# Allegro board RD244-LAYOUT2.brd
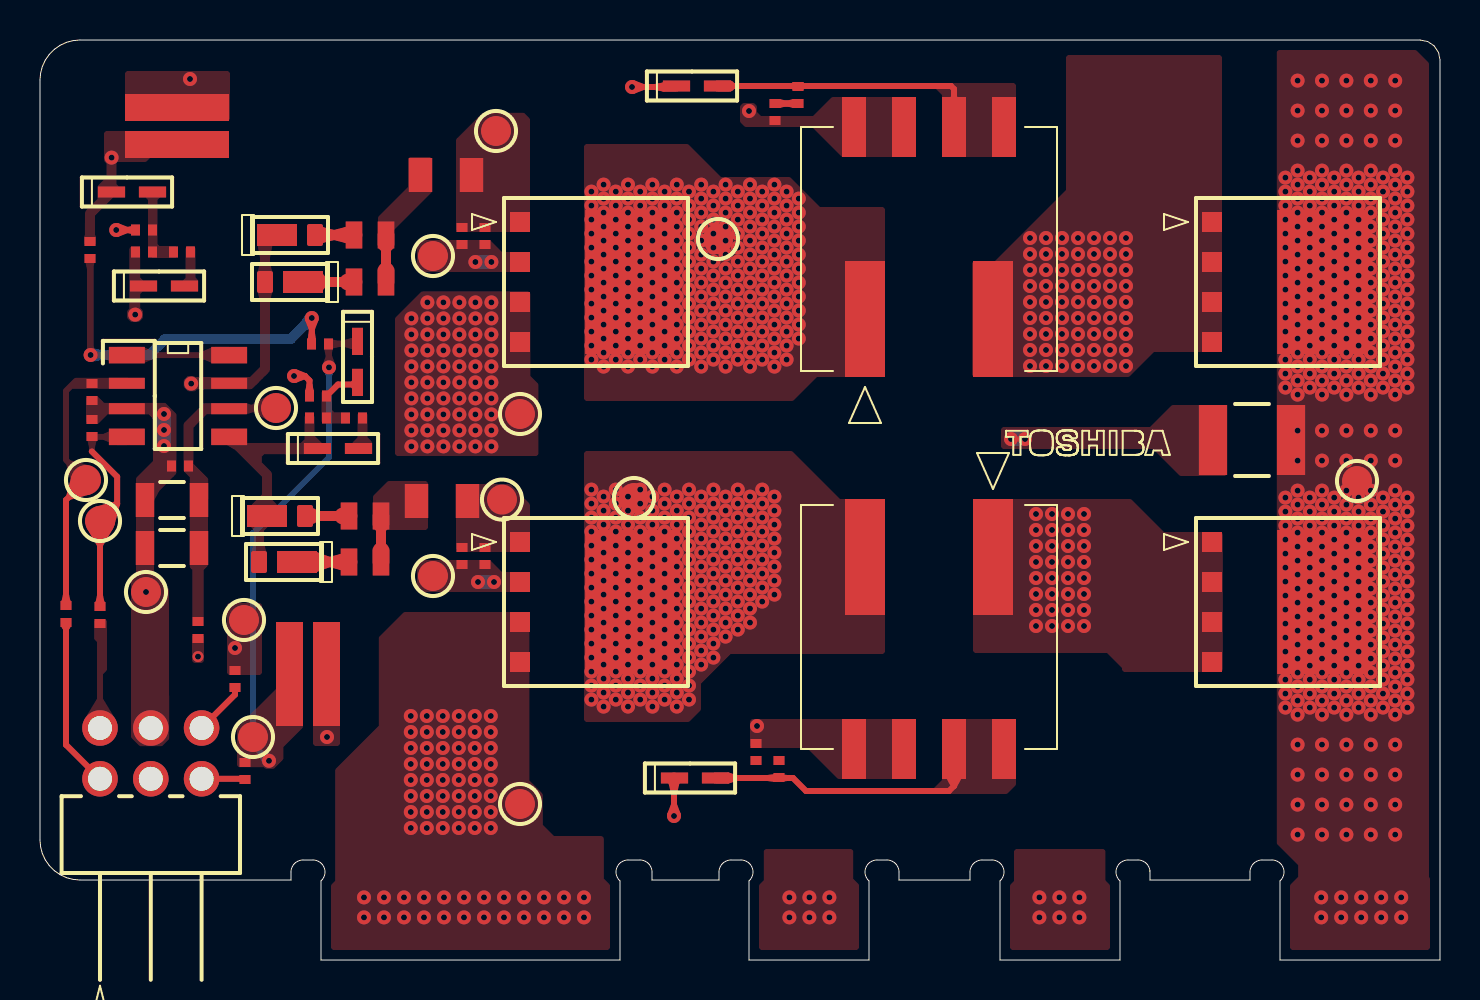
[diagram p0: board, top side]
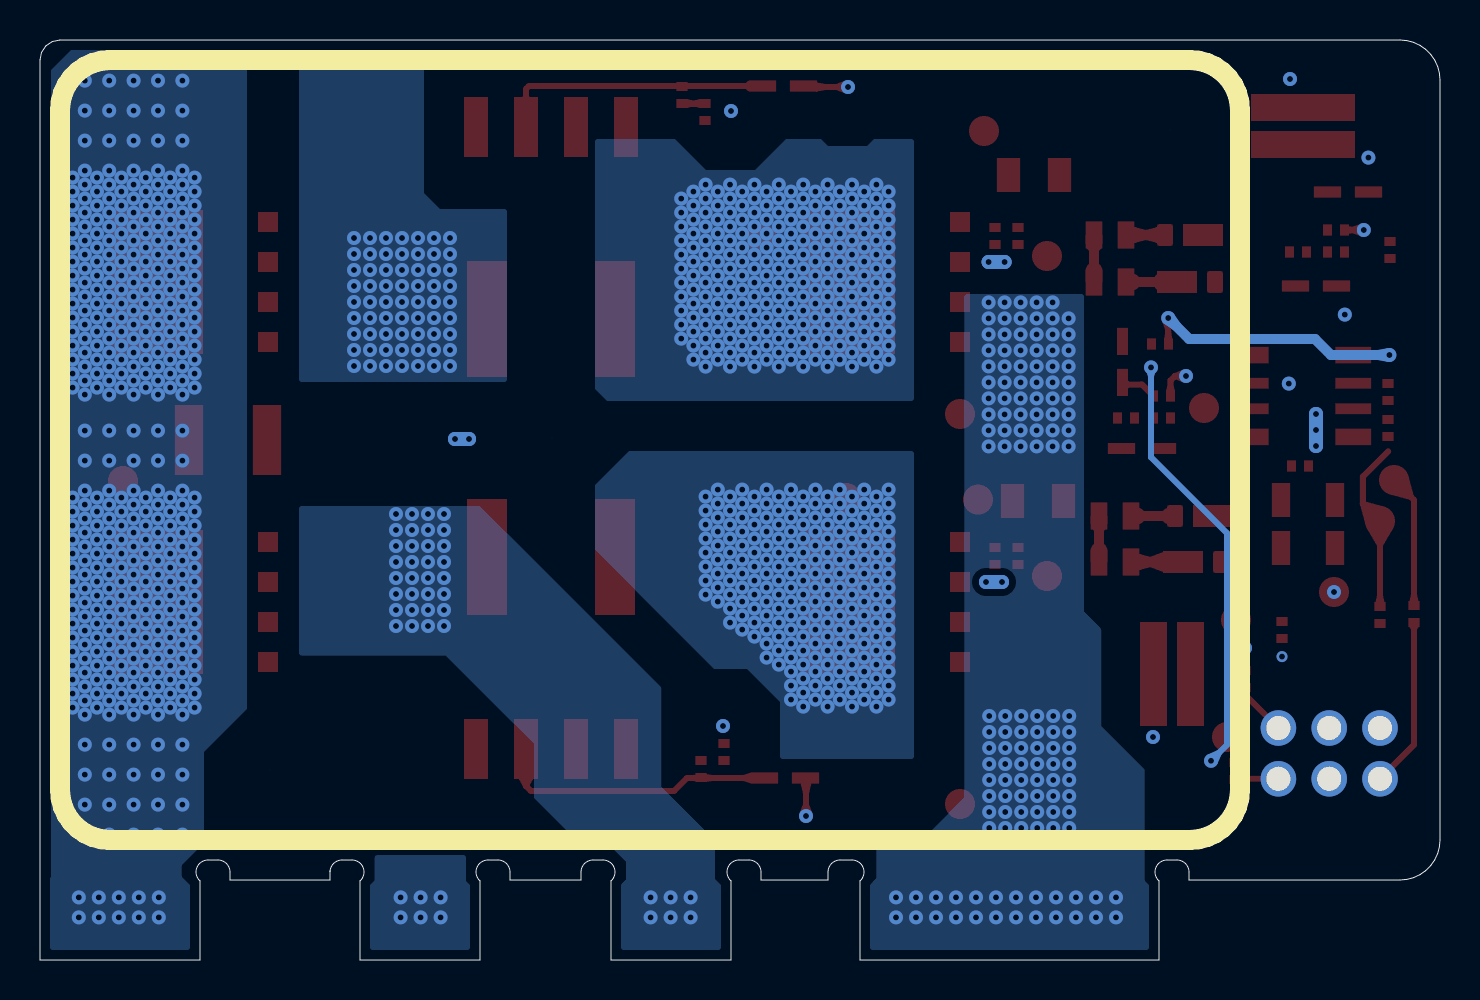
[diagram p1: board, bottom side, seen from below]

Outline 70 x 46 mm; copper layers: TOP, CONDUCTIVE2, CONDUCTIVE3, CONDUCTIVE4, CONDUCTIVE5, BOTTOM. Coordinates in mm from the lower left corner of the outline.
Outline path: 0,44 0.03,44.35 0.12,44.68 0.27,45 0.47,45.29 0.71,45.53 1,45.73 1.32,45.88 1.65,45.97 2,46 69,46 69.39,45.92 69.71,45.71 69.93,45.37 70,45 70,0 62,0 62,3.95 arc(62.16,4.61) 61.6,5 61.1,5 arc(60.68,4.82) 60.5,4.4 60.5,4 55.5,4 55.5,4.45 55.5,4.45 arc(55.31,4.84) 54.9,5 54.4,5 arc(53.84,4.61) 54,3.95 54,0 48,0 48,3.95 arc(48.16,4.61) 47.6,5 47.1,5 arc(46.68,4.82) 46.5,4.4 46.5,4 42.95,4 42.95,4.4 arc(42.77,4.82) 42.35,5 41.85,5 arc(41.29,4.61) 41.45,3.95 41.45,0 35.45,0 35.45,3.95 arc(35.61,4.61) 35.05,5 34.55,5 arc(34.13,4.82) 33.95,4.4 33.95,4 30.6,4 30.6,4.4 arc(30.42,4.82) 30,5 29.4,5 arc(28.84,4.61) 29,3.95 29,0 14.05,0 14.05,3.95 arc(14.21,4.61) 13.65,5 13.15,5 arc(12.73,4.82) 12.55,4.4 12.55,4 2,4 1.65,4.03 1.32,4.12 1,4.27 0.71,4.47 0.47,4.71 0.27,5 0.12,5.32 0.03,5.65 0,6 0,44

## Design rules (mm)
constraint set DEFAULT: 

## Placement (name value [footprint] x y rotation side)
C601  -  [FTP_65]  2.6 28.4 90 top
C602  -  [FTP_65]  2.6 26.6 270 top
C603  -  [FTP_15]  6.6 20.6 0 top
C604  -  [FTP_15]  6.6 23 0 top
C605  -  [FTP_65]  7 24.7 0 top
C606  -  [FTP_65]  36.75 42.4 90 top
C607  -  [FTP_65]  5.2 36.5 0 top
C608  -  [FTP_65]  35.8 10.4 270 top
C609  -  [FTP_65]  13.9 28.2 0 top
C610  -  [DC835R1AKP]  60.6 26 0 top
C611  -  [FTP_65]  22.25 36.2 90 top
C612  -  [FTP_65]  22.25 20.2 90 top
CN602  -  [CTP100H0ATP]  3 9.06 0 top
D601  -  [LOCAL_IDL02G65C5_A]  62.8 33.9 270 top
D602  -  [FTP_20]  32.85 43.7 180 top
D603  -  [US2H_A]  12.5 33.9 180 top
D604  -  [US2H_A]  12.5 36.25 0 top
D605  -  [FTP_20]  6.2 33.7 180 top
D606  -  [FTP_20]  4.6 38.4 180 top
D607  -  [LOCAL_IDL02G65C5_A]  62.8 17.9 270 top
D608  -  [FTP_20]  32.75 9.1 180 top
D609  -  [US2H_A]  12.2 19.9 180 top
D610  -  [US2H_A]  12 22.2 0 top
D611  -  [FTP_20]  14.9 25.57 180 top
D612  -  [FTP_20]  15.88 29.91 90 top
DP601  -  [DTP815]  2.3 24 0 top
DP602  -  [DTP815]  3 21.95 0 top
DP603  -  [DTP815]  11.8 27.6 0 top
DP604  -  [DTP815]  5.3 18.4 0 top
DP605  -  [DTP815]  10.2 17 0 top
DP606  -  [DTP815]  22.8 41.45 0 top
DP607  -  [DTP815]  33.9 36.05 0 top
DP608  -  [DTP815]  24 27.3 0 top
DP609  -  [DTP815]  10.65 11.15 0 top
DP610  -  [DTP815]  23.1 23.02 0 top
DP611  -  [DTP815]  29.7 23.1 0 top
DP612  -  [DTP815]  24 7.8 0 top
DP613  -  [DTP815]  65.85 23.95 0 top
DP614  -  [DTP815]  19.65 35.2 0 top
DP615  -  [DTP815]  19.65 19.2 0 top
IC601  -  [FTP_112]  6.9 28.2 270 top
L601  -  [FTP_55]  20.3 39.25 0 top
L602  -  [FTP_55]  20.1 22.95 0 top
NOREF  -  []  47.1 24.05 0 top
NOREF#2  -  [unnamed#2]  39.5 25.5 180 bottom
Q601  -  [LOCAL_DFN8X8_A]  28.2 33.9 270 top
Q602  -  [LOCAL_DFN8X8_A]  28.2 17.9 270 top
R601  -  [KC00050AKP]  7.9 16.5 90 top
R602  -  [KCK02780AKP]  6.85 41.7 270 top
R603  -  [KC00050AKP]  37.9 43.25 90 top
R604  -  [DR810K]  16.5 36.25 0 top
R605  -  [DR810K]  16.5 33.9 0 top
R606  -  [KC00050AKP]  21.1 36.2 90 top
R607  -  [KC00050AKP]  5.2 35.4 0 top
R608  -  [KC00050AKP]  7.1 35.4 180 top
R609  -  [KC00050AKP]  2.5 35.5 270 top
R610  -  [KCK02780AKP]  13.4 14.3 180 top
R611  -  [KC00050AKP]  36.95 9.55 270 top
R612  -  [DR810K]  16.25 22.2 0 top
R613  -  [DR810K]  16.25 19.9 0 top
R614  -  [KC00050AKP]  21.1 20.2 90 top
R615  -  [KC00050AKP]  13.9 27.1 0 top
R616  -  [KC00050AKP]  15.7 27.1 180 top
R617  -  [KC00050AKP]  14 30.8 180 top
R618  -  [KC00050AKP]  1.3 17.3 270 top
R619  -  [KC00050AKP]  3 17.25 270 top
R622  -  [KC00050AKP]  10.25 9.45 270 top
R623  -  [KC00050AKP]  9.75 14.05 270 top
T601  -  [LOCAL_PH9505_100NLT_A]  44.45 32.05 270 top
T602  -  [LOCAL_PH9505_100NLT_A]  44.45 20.15 90 top

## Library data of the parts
C601 C602 C605-C609 C611 C612 = PRT_52: alternate symbols: (T:FTP_65;B:FTP_66)
C603 C604 = PRT_46: alternate symbols: (T:FTP_15;B:FTP_16)
C610 = K03S007Y: alternate symbols: (T:DC835R1AKP;B:DC835R1BKP)
CN602 = K22S0030: alternate symbols: (T:CTP100H0ATP;B:CTP100H0BTP)
D601 D607 = TRS12V65H: alternate symbols: (T:Local_IDL02G65C5_A;B:Local_IDL02G65C5_B)
D602 D605 D606 D608 D611 D612 = PRT_27: alternate symbols: (T:FTP_20;B:FTP_22)
D603 D604 D609 D610 = CUHS15S30: alternate symbols: (T:US2H_A;B:US2H_B)
DP601-DP615 = DTP815: alternate symbols: (T:DTP815;B:DTP915)
IC601 = PRT_63: alternate symbols: (T:FTP_112;B:FTP_113)
L601 L602 = PRT_30: alternate symbols: (T:FTP_55;B:FTP_56)
Q601 Q602 = NchMOSFET_DFN8x8-01: alternate symbols: (T:Local_DFN8x8_A;B:Local_DFN8x8_B)
R601 R603 R606-R609 R611 R614-R619 R622 R623 = GDM010004481: alternate symbols: (T:KC00050AKP;B:KC00050BKP)
R602 R610 = K01S003U: alternate symbols: (T:KCK02780AKP;B:KCK02780BKP)
R604 R605 R612 R613 = R2012: alternate symbols: (T:DR810K;B:DR910K)
T601 T602 = PH9505_100NLT: alternate symbols: (T:Local_PH9505_100NLT_A;B:Local_PH9505_100NLT_B)

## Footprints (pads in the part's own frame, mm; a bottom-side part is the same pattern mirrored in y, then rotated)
CTP100H0ATP
  round 1.778 hole 1.2: 1(0,0) 2(0,2.54) 3(2.54,0) 4(2.54,2.54) 5(5.08,0) 6(5.08,2.54)
DC835R1AKP
  rect 1.41x3.5 smd: 1(-1.95,0) 2(1.95,0)
DR810K
  rect 0.83x1.35 smd: 1(-0.8,0) 2(0.8,0)
DTP815
  round 1.5 smd: 1(0,0)
FTP_15
  rect 0.92x1.7 smd: 1(-1.35,0) 2(1.35,0)
FTP_20
  rect 1.36x0.55 smd: A(-1.025,0) C(1.025,0)
FTP_55
  rect 1.17x1.7 smd: 1(-1.275,0) 2(1.275,0)
FTP_65
  rect 0.45x0.55 smd: 1(-0.425,0) 2(0.425,0)
FTP_112
  rect 0.825x1.795 smd: 1(-2.042,-2.558) 4(2.042,-2.558) 5(2.042,2.558) 8(-2.042,2.558)
  rect 0.55x1.795 smd: 2(-0.635,-2.558) 3(0.635,-2.558) 6(0.635,2.558) 7(-0.635,2.558)
KC00050AKP
  rect 0.45x0.55 smd: 1(-0.425,0) 2(0.425,0)
KCK02780AKP
  rect 1.35x5.2 smd: 1(-0.925,0) 2(0.925,0)
LOCAL_DFN8X8_A
  rect 1x1 smd: 1(-3,-4.2) 2(-1,-4.2) 3(1,-4.2) 4(3,-4.2)
  rect 7.2x4.75 smd: 5(0,1.43)
LOCAL_IDL02G65C5_A
  rect 1x1 smd: 1(-3,-4.2) 2(-1,-4.2) 3(1,-4.2) 4(3,-4.2)
  rect 7.2x4.75 smd: 5(0,1.43)
LOCAL_PH9505_100NLT_A
  rect 5.8x2 smd: 1(0,-3.2) 2(0,3.2)
  rect 3x1.2 smd: 3(-9.6,3.75) 4(-9.6,1.25) 5(-9.6,-1.25) 6(-9.6,-3.75)
unnamed#2
  round 0.01 hole 3.2 unplated: (-19,-16) (-4.9,0.6) (26,16)
US2H_A
  custom 0.2x0.2 smd: A(1.25,0)
  rect 2x1.1 smd: C(-0.65,0)

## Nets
VCC18R0_1: CN602.3 IC601.1 IC601.8 R601.1 R609.2 R617.2
CSA: CN602.6 D602.C D606.C DP605.1 R602.2 R609.1 R623.1 R623.2
CSB: CN602.5 D608.C D612.C DP609.1 R610.2 R617.1 R622.1 R622.2
GDA: C601.2 CN602.1 DP601.1 IC601.2 R618.1 R618.2
GDB: C602.2 CN602.2 DP602.1 IC601.4 R619.1 R619.2
PN: C601.1 C602.1 C603.1 C604.1 C605.1 C606.1 C607.1 C608.1 C609.1 C611.1 C612.1 CN602.4 DP604.1 DP614.1 DP615.1 IC601.3 Q601.2 Q602.2 R602.1 R606.1 R610.1 R614.1 T601.5 T602.4
SIG0017: C612.2 D609.C D610.A DP610.1 L602.1 L602.2 Q602.1 R612.1 R612.2 R613.1 R613.2 R614.2
SIG0019: C609.2 D609.A D610.C D611.A D611.C D612.A IC601.5 R615.1 R615.2 R616.1 R616.2
SIG00110: C611.2 D603.C D604.A DP606.1 L601.1 L601.2 Q601.1 R604.1 R604.2 R605.1 R605.2 R606.2
SIG00112: C607.2 D603.A D604.C D605.A D605.C D606.A IC601.7 R607.1 R607.2 R608.1 R608.2
SIG00119: C603.2 C604.2 C605.2 DP603.1 IC601.6 R601.2
SIG00120: D607.3 D607.4 T602.1
SIG00125: DP607.1 Q601.5 T601.1
SIG00126: C608.2 D608.A R611.1 R611.2 T602.5
SIG00127: C606.2 D602.A R603.1 R603.2 T601.4
SIG00130: D601.3 D601.4 T601.2
SIG00131: DP611.1 Q602.5 T602.2
SIG00132: C610.1 C610.2 D601.5 D607.5 DP608.1 DP612.1 DP613.1 Q601.3 Q601.4 Q602.3 Q602.4

Pads without a net: D601 1 2; D607 1 2; T601 3 6; T602 3 6

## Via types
v1: diameter 0.7, hole 0.3, TOP to BOTTOM, 1140 vias
v2: diameter 0.55, hole 0.3, TOP to BOTTOM, 1 via

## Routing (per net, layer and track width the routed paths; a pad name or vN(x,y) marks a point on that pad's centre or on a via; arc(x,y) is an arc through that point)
VCC18R0_1: length 13.1
  TOP w0.3: v1(13.59,32.1) 13.59,30.98
  TOP w0.42: 13.59,30.98 13.59,30.8
  BOTTOM w0.5: v1(13.59,32.1) 12.54,31.05 6.25,31.05 5.45,30.25 v1(2.53,30.25)
  vias: v2(7.9,15.17)
CSA: length 62.2
  TOP w0.3: v1(29.6,43.65) 31.18,43.65 ; R623.2 9.75,13.27 CN602.6
  TOP w0.45: 31.18,43.65 31.82,43.65
  CONDUCTIVE4 w0.3: v1(3.58,40.12) 5.63,40.12 8.65,37.1 ; 8.65,37.1 9.05,37.1 ; 8.65,37.1 9.05,36.7 ; 9.05,37.1 9.05,36.7 ; 9.05,37.1 9.05,43.3 10.9,45.15 20.5,45.15 21.35,44.3 28.95,44.3 v1(29.6,43.65) ; 9.05,36.7 9.05,16.3 v1(9.75,15.6)
CSB: length 48.5
  TOP w0.3: v1(31.7,7.2) 31.7,8.89 ; CN602.5 10.08,9.06
  TOP w0.38: 10.08,9.06 10.25,9.06
  TOP w0.55: 31.7,8.89 31.7,9.1
  CONDUCTIVE4 w0.3: v1(11.45,9.96) 16.01,5.4 26.9,5.4 28.7,7.2 v1(31.7,7.2)
  BOTTOM w0.3: v1(11.45,9.96) 10.65,10.76 10.65,21.34 14.45,25.14 v1(14.45,29.63)
GDA: length 15.2
  TOP w0.3: 1.3,17.9 1.3,23 DP601.1 ; 1.3,16.7 1.3,10.76 CN602.1
  TOP w0.45: R618.1 1.3,17.9 ; 1.3,16.7 R618.2
GDB: length 8.6
  TOP w0.3: 3,17.85 DP602.1 3.86,22.81 3.86,24.16 2.59,25.43
  TOP w0.45: R619.1 3,17.85
PN: length 104.3
  TOP w0.3: v1(12.7,29.2) 13.25,29.2 13.47,28.98 13.47,28.38 ; v1(3.81,36.5) 4.73,36.5
  TOP w0.45: 4.73,36.5 C607.1 ; 13.47,28.38 C609.1
  CONDUCTIVE3 w0.3: v1(35.45,42.45) 20.05,42.45 17.55,44.95 8.4,44.95 v1(7.5,44.05) 7.5,32.6 5.3,30.4 v1(5.3,18.4) 9.95,18.4 14.35,14 v1(14.35,11.15) 14.35,9 17.85,5.5 26,5.5 26.7,6.2 32.45,6.2 35.85,9.6 v1(35.85,11.7)
  BOTTOM w0.7: v1(21.77,34.9) v1(22.57,34.9) ; v1(6.2,25.7) v1(6.2,26.5) v1(6.2,27.3) ; v1(22.7,18.9) v1(21.9,18.9)
SIG0017: length 7.1
  TOP w0.5: 15.14,22.2 13.56,22.2 ; 17.05,21.8 17.05,20.47 ; 15.14,19.9 13.59,19.9
  TOP w0.8: 13.56,22.2 D610.A
  TOP w0.83: R612.1 15.14,22.2 ; R612.2 17.05,21.8 ; 17.05,20.47 R613.2 ; R613.1 15.14,19.9
  TOP w1.1: 13.59,19.9 D609.C
SIG0019: length 1.7
  TOP w0.3: 15.79,28.77 14.9,28.77 14.32,28.2
  TOP w0.55: 15.8,28.77 15.79,28.77
SIG00110: length 6.8
  TOP w0.5: 17.3,35.8 17.3,34.47 ; 13.77,33.9 15.39,33.9 ; 14.06,36.25 15.39,36.25
  TOP w0.8: D604.A 14.06,36.25
  TOP w0.83: 17.3,34.47 R605.2 ; 15.39,36.25 R604.1 ; 15.39,33.9 R605.1 ; R604.2 17.3,35.8
  TOP w1.1: D603.C 13.77,33.9
SIG00112: length 5.6
  CONDUCTIVE4 w0.5: v1(7.56,28.82) 7.56,31.14 6.43,32.27 v1(4.76,32.27)
SIG00120:
  vias: v1(37.47,3.13) v1(37.47,2.13) v1(38.47,3.13) v1(38.47,2.13) v1(39.47,3.13) v1(39.47,2.13) v1(49.8,22.3) v1(49.8,21.5) v1(49.8,20.7) v1(49.8,19.9) v1(49.8,19.1) v1(49.8,18.3) v1(49.8,17.5) v1(49.8,16.7) v1(50.6,22.3) v1(50.6,21.5) v1(50.6,20.7) v1(50.6,19.9) v1(50.6,19.1) v1(50.6,18.3) v1(50.6,17.5) v1(50.6,16.7) v1(51.4,22.3) v1(51.4,21.5) v1(51.4,20.7) v1(51.4,19.9) v1(51.4,19.1) v1(51.4,18.3) v1(51.4,17.5) v1(51.4,16.7) v1(52.2,22.3) v1(52.2,21.5) v1(52.2,20.7) v1(52.2,19.9) v1(52.2,19.1) v1(52.2,18.3) v1(52.2,17.5) v1(52.2,16.7)
SIG00125:
  vias: v1(27.57,38.42) v1(27.57,37.72) v1(27.57,37.02) v1(27.57,36.32) v1(27.57,35.62) v1(27.57,34.92) v1(27.57,34.22) v1(27.57,33.52) v1(27.57,32.82) v1(27.57,32.12) v1(27.57,31.42) v1(27.57,30.72) v1(27.57,30.02) v1(28.18,38.77) v1(28.18,38.07) v1(28.18,37.37) v1(28.18,36.67) v1(28.18,35.97) v1(28.18,35.27) v1(28.18,34.57) v1(28.18,33.87) v1(28.18,33.17) v1(28.18,32.47) v1(28.18,31.77) v1(28.18,31.07) v1(28.18,30.37) v1(28.18,29.67) v1(28.79,38.42) v1(28.79,37.72) v1(28.79,37.02) v1(28.79,36.32) v1(28.79,35.62) v1(28.79,34.92) v1(28.79,34.22) v1(28.79,33.52) v1(28.79,32.82) v1(28.79,32.12) v1(28.79,31.42) v1(28.79,30.72) v1(28.79,30.02) v1(29.4,38.77) v1(29.4,38.07) v1(29.4,37.37) v1(29.4,36.67) v1(29.4,35.97) v1(29.4,35.27) v1(29.4,34.57) v1(29.4,33.87) v1(29.4,33.17) v1(29.4,32.47) v1(29.4,31.77) v1(29.4,31.07) v1(29.4,30.37) v1(29.4,29.67) v1(30.01,38.42) v1(30.01,37.72) v1(30.01,37.02) v1(30.01,36.32) v1(30.01,35.62) v1(30.01,34.92) v1(30.01,34.22) v1(30.01,33.52) v1(30.01,32.82) v1(30.01,32.12) v1(30.01,31.42) v1(30.01,30.72) v1(30.01,30.02) v1(30.62,38.77) v1(30.62,38.07) v1(30.62,37.37) v1(30.62,36.67) v1(30.62,35.97) v1(30.62,35.27) v1(30.62,34.57) v1(30.62,33.87) v1(30.62,33.17) v1(30.62,32.47) v1(30.62,31.77) v1(30.62,31.07) v1(30.62,30.37) v1(30.62,29.67) v1(31.23,38.42) v1(31.23,37.72) v1(31.23,37.02) v1(31.23,36.32) v1(31.23,35.62) v1(31.23,34.92) v1(31.23,34.22) v1(31.23,33.52) v1(31.23,32.82) v1(31.23,32.12) v1(31.23,31.42) v1(31.23,30.72) v1(31.23,30.02) v1(31.84,38.77) v1(31.84,38.07) v1(31.84,37.37) v1(31.84,36.67) v1(31.84,35.97) v1(31.84,35.27) v1(31.84,34.57) v1(31.84,33.87) v1(31.84,33.17) v1(31.84,32.47) v1(31.84,31.77) v1(31.84,31.07) v1(31.84,30.37) v1(31.84,29.67) v1(32.45,38.42) v1(32.45,37.72) v1(32.45,37.02) v1(32.45,36.32) v1(32.45,35.62) v1(32.45,34.92) v1(32.45,34.22) v1(32.45,33.52) v1(32.45,32.82) v1(32.45,32.12) v1(32.45,31.42) v1(32.45,30.72) v1(32.45,30.02) v1(33.06,38.77) v1(33.06,38.07) v1(33.06,37.37) v1(33.06,36.67) v1(33.06,35.97) v1(33.06,35.27) v1(33.06,34.57) v1(33.06,33.87) v1(33.06,33.17) v1(33.06,32.47) v1(33.06,31.77) v1(33.06,31.07) v1(33.06,30.37) v1(33.06,29.67) v1(33.67,38.42) v1(33.67,37.72) v1(33.67,37.02) v1(33.67,36.32) v1(33.67,35.62) v1(33.67,34.92) v1(33.67,34.22) v1(33.67,33.52) v1(33.67,32.82) v1(33.67,32.12) v1(33.67,31.42) v1(33.67,30.72) v1(33.67,30.02) v1(34.28,38.77) v1(34.28,38.07) v1(34.28,37.37) v1(34.28,36.67) v1(34.28,35.97) v1(34.28,35.27) v1(34.28,34.57) v1(34.28,33.87) v1(34.28,33.17) v1(34.28,32.47) v1(34.28,31.77) v1(34.28,31.07) v1(34.28,30.37) v1(34.28,29.67) v1(34.89,38.42) v1(34.89,37.72) v1(34.89,37.02) v1(34.89,36.32) v1(34.89,35.62) v1(34.89,34.92) v1(34.89,34.22) v1(34.89,33.52) v1(34.89,32.82) v1(34.89,32.12) v1(34.89,31.42) v1(34.89,30.72) v1(34.89,30.02) v1(35.5,38.77) v1(35.5,38.07) v1(35.5,37.37) v1(35.5,36.67) v1(35.5,35.97) v1(35.5,35.27) v1(35.5,34.57) v1(35.5,33.87) v1(35.5,33.17) v1(35.5,32.47) v1(35.5,31.77) v1(35.5,31.07) v1(35.5,30.37) v1(35.5,29.67) v1(36.11,38.42) v1(36.11,37.72) v1(36.11,37.02) v1(36.11,36.32) v1(36.11,35.62) v1(36.11,34.92) v1(36.11,34.22) v1(36.11,33.52) v1(36.11,32.82) v1(36.11,32.12) v1(36.11,31.42) v1(36.11,30.72) v1(36.11,30.02) v1(36.72,38.77) v1(36.72,38.07) v1(36.72,37.37) v1(36.72,36.67) v1(36.72,35.97) v1(36.72,35.27) v1(36.72,34.57) v1(36.72,33.87) v1(36.72,33.17) v1(36.72,32.47) v1(36.72,31.77) v1(36.72,31.07) v1(36.72,30.37) v1(36.72,29.67) v1(37.33,38.42) v1(37.33,37.72) v1(37.33,37.02) v1(37.33,36.32) v1(37.33,35.62) v1(37.33,34.92) v1(37.33,34.22) v1(37.33,33.52) v1(37.33,32.82) v1(37.33,32.12) v1(37.33,31.42) v1(37.33,30.72) v1(37.33,30.02) v1(37.94,38.07) v1(37.94,37.37) v1(37.94,36.67) v1(37.94,35.97) v1(37.94,35.27) v1(37.94,34.57) v1(37.94,33.87) v1(37.94,33.17) v1(37.94,32.47) v1(37.94,31.77) v1(37.94,31.07)
SIG00126: length 14.1
  TOP w0.3: 36.95,9.1 37.65,9.1 38.3,8.45 45.45,8.45 45.7,8.7 45.7,9.65 ; 34.38,9.1 36.77,9.1
  TOP w0.4: 36.77,9.1 36.95,9.1
  TOP w0.55: D608.A 34.38,9.1
  TOP w1.2: 45.7,9.65 T602.5
SIG00127: length 14.9
  TOP w0.3: 37.73,43.7 34.48,43.7 ; 45.7,42.59 45.7,43.55 45.55,43.7 38.07,43.7 ; 36.93,42.83 37.72,42.83
  TOP w0.4: 38.07,43.7 37.73,43.7
  TOP w0.45: 37.72,42.83 R603.1 ; C606.2 36.93,42.83
  TOP w0.55: 34.48,43.7 D602.A
  TOP w1.2: T601.4 45.7,42.59
SIG00130:
  vias: v1(49.5,36.1) v1(49.5,35.3) v1(49.5,34.5) v1(49.5,33.7) v1(49.5,32.9) v1(49.5,32.1) v1(49.5,31.3) v1(49.5,30.5) v1(49.5,29.7) v1(49.97,3.13) v1(49.97,2.13) v1(50.3,36.1) v1(50.3,35.3) v1(50.3,34.5) v1(50.3,33.7) v1(50.3,32.9) v1(50.3,32.1) v1(50.3,31.3) v1(50.3,30.5) v1(50.3,29.7) v1(50.97,3.13) v1(50.97,2.13) v1(51.1,36.1) v1(51.1,35.3) v1(51.1,34.5) v1(51.1,33.7) v1(51.1,32.9) v1(51.1,32.1) v1(51.1,31.3) v1(51.1,30.5) v1(51.1,29.7) v1(51.9,36.1) v1(51.9,35.3) v1(51.9,34.5) v1(51.9,33.7) v1(51.9,32.9) v1(51.9,32.1) v1(51.9,31.3) v1(51.9,30.5) v1(51.9,29.7) v1(51.97,3.13) v1(51.97,2.13) v1(52.7,36.1) v1(52.7,35.3) v1(52.7,34.5) v1(52.7,33.7) v1(52.7,32.9) v1(52.7,32.1) v1(52.7,31.3) v1(52.7,30.5) v1(52.7,29.7) v1(53.5,36.1) v1(53.5,35.3) v1(53.5,34.5) v1(53.5,33.7) v1(53.5,32.9) v1(53.5,32.1) v1(53.5,31.3) v1(53.5,30.5) v1(53.5,29.7) v1(54.3,36.1) v1(54.3,35.3) v1(54.3,34.5) v1(54.3,33.7) v1(54.3,32.9) v1(54.3,32.1) v1(54.3,31.3) v1(54.3,30.5) v1(54.3,29.7)
SIG00131:
  vias: v1(27.57,23.52) v1(27.57,22.82) v1(27.57,22.12) v1(27.57,21.42) v1(27.57,20.72) v1(27.57,20.02) v1(27.57,19.32) v1(27.57,18.62) v1(27.57,17.92) v1(27.57,17.22) v1(27.57,16.52) v1(27.57,15.82) v1(27.57,15.12) v1(27.57,14.42) v1(27.57,13.72) v1(27.57,13.02) v1(28.18,23.17) v1(28.18,22.47) v1(28.18,21.77) v1(28.18,21.07) v1(28.18,20.37) v1(28.18,19.67) v1(28.18,18.97) v1(28.18,18.27) v1(28.18,17.57) v1(28.18,16.87) v1(28.18,16.17) v1(28.18,15.47) v1(28.18,14.77) v1(28.18,14.07) v1(28.18,13.37) v1(28.18,12.67) v1(28.79,23.52) v1(28.79,22.82) v1(28.79,22.12) v1(28.79,21.42) v1(28.79,20.72) v1(28.79,20.02) v1(28.79,19.32) v1(28.79,18.62) v1(28.79,17.92) v1(28.79,17.22) v1(28.79,16.52) v1(28.79,15.82) v1(28.79,15.12) v1(28.79,14.42) v1(28.79,13.72) v1(28.79,13.02) v1(29.4,23.17) v1(29.4,22.47) v1(29.4,21.77) v1(29.4,21.07) v1(29.4,20.37) v1(29.4,19.67) v1(29.4,18.97) v1(29.4,18.27) v1(29.4,17.57) v1(29.4,16.87) v1(29.4,16.17) v1(29.4,15.47) v1(29.4,14.77) v1(29.4,14.07) v1(29.4,13.37) v1(29.4,12.67) v1(30.01,23.52) v1(30.01,22.82) v1(30.01,22.12) v1(30.01,21.42) v1(30.01,20.72) v1(30.01,20.02) v1(30.01,19.32) v1(30.01,18.62) v1(30.01,17.92) v1(30.01,17.22) v1(30.01,16.52) v1(30.01,15.82) v1(30.01,15.12) v1(30.01,14.42) v1(30.01,13.72) v1(30.01,13.02) v1(30.62,23.17) v1(30.62,22.47) v1(30.62,21.77) v1(30.62,21.07) v1(30.62,20.37) v1(30.62,19.67) v1(30.62,18.97) v1(30.62,18.27) v1(30.62,17.57) v1(30.62,16.87) v1(30.62,16.17) v1(30.62,15.47) v1(30.62,14.77) v1(30.62,14.07) v1(30.62,13.37) v1(30.62,12.67) v1(31.23,23.52) v1(31.23,22.82) v1(31.23,22.12) v1(31.23,21.42) v1(31.23,20.72) v1(31.23,20.02) v1(31.23,19.32) v1(31.23,18.62) v1(31.23,17.92) v1(31.23,17.22) v1(31.23,16.52) v1(31.23,15.82) v1(31.23,15.12) v1(31.23,14.42) v1(31.23,13.72) v1(31.23,13.02) v1(31.84,23.17) v1(31.84,22.47) v1(31.84,21.77) v1(31.84,21.07) v1(31.84,20.37) v1(31.84,19.67) v1(31.84,18.97) v1(31.84,18.27) v1(31.84,17.57) v1(31.84,16.87) v1(31.84,16.17) v1(31.84,15.47) v1(31.84,14.77) v1(31.84,14.07) v1(31.84,13.37) v1(31.84,12.67) v1(32.45,23.52) v1(32.45,22.82) v1(32.45,22.12) v1(32.45,21.42) v1(32.45,20.72) v1(32.45,20.02) v1(32.45,19.32) v1(32.45,18.62) v1(32.45,17.92) v1(32.45,17.22) v1(32.45,16.52) v1(32.45,15.82) v1(32.45,15.12) v1(32.45,14.42) v1(32.45,13.72) v1(32.45,13.02) v1(33.06,23.17) v1(33.06,22.47) v1(33.06,21.77) v1(33.06,21.07) v1(33.06,20.37) v1(33.06,19.67) v1(33.06,18.97) v1(33.06,18.27) v1(33.06,17.57) v1(33.06,16.87) v1(33.06,16.17) v1(33.06,15.47) v1(33.06,14.77) v1(33.67,23.52) v1(33.67,22.82) v1(33.67,22.12) v1(33.67,21.42) v1(33.67,20.72) v1(33.67,20.02) v1(33.67,19.32) v1(33.67,18.62) v1(33.67,17.92) v1(33.67,17.22) v1(33.67,16.52) v1(33.67,15.82) v1(33.67,15.12) v1(34.28,23.17) v1(34.28,22.47) v1(34.28,21.77) v1(34.28,21.07) v1(34.28,20.37) v1(34.28,19.67) v1(34.28,18.97) v1(34.28,18.27) v1(34.28,17.57) v1(34.28,16.87) v1(34.28,16.17) v1(34.89,23.52) v1(34.89,22.82) v1(34.89,22.12) v1(34.89,21.42) v1(34.89,20.72) v1(34.89,20.02) v1(34.89,19.32) v1(34.89,18.62) v1(34.89,17.92) v1(34.89,17.22) v1(34.89,16.52) v1(35.5,23.17) v1(35.5,22.47) v1(35.5,21.77) v1(35.5,21.07) v1(35.5,20.37) v1(35.5,19.67) v1(35.5,18.97) v1(35.5,18.27) v1(35.5,17.57) v1(35.5,16.87) v1(36.11,23.52) v1(36.11,22.82) v1(36.11,22.12) v1(36.11,21.42) v1(36.11,20.72) v1(36.11,20.02) v1(36.11,19.32) v1(36.11,18.62) v1(36.11,17.92) v1(36.72,23.17) v1(36.72,22.47) v1(36.72,21.77) v1(36.72,21.07) v1(36.72,20.37) v1(36.72,19.67) v1(36.72,18.97) v1(36.72,18.27)
SIG00132: length 0.7
  BOTTOM w0.7: v1(48.55,26.05) v1(49.25,26.05)
  vias: v1(16.2,3.13) v1(16.2,2.13) v1(17.2,3.13) v1(17.2,2.13) v1(18.2,3.13) v1(18.2,2.13) v1(18.54,12.2) v1(18.54,11.4) v1(18.54,10.6) v1(18.54,9.8) v1(18.54,9) v1(18.54,8.2) v1(18.54,7.4) v1(18.54,6.6) v1(18.57,32.08) v1(18.57,31.28) v1(18.57,30.48) v1(18.57,29.68) v1(18.57,28.88) v1(18.57,28.08) v1(18.57,27.28) v1(18.57,26.48) v1(18.57,25.68) v1(19.2,3.13) v1(19.2,2.13) v1(19.34,12.2) v1(19.34,11.4) v1(19.34,10.6) v1(19.34,9.8) v1(19.34,9) v1(19.34,8.2) v1(19.34,7.4) v1(19.34,6.6) v1(19.37,32.88) v1(19.37,32.08) v1(19.37,31.28) v1(19.37,30.48) v1(19.37,29.68) v1(19.37,28.88) v1(19.37,28.08) v1(19.37,27.28) v1(19.37,26.48) v1(19.37,25.68) v1(20.14,12.2) v1(20.14,11.4) v1(20.14,10.6) v1(20.14,9.8) v1(20.14,9) v1(20.14,8.2) v1(20.14,7.4) v1(20.14,6.6) v1(20.17,32.88) v1(20.17,32.08) v1(20.17,31.28) v1(20.17,30.48) v1(20.17,29.68) v1(20.17,28.88) v1(20.17,28.08) v1(20.17,27.28) v1(20.17,26.48) v1(20.17,25.68) v1(20.2,3.13) v1(20.2,2.13) v1(20.94,12.2) v1(20.94,11.4) v1(20.94,10.6) v1(20.94,9.8) v1(20.94,9) v1(20.94,8.2) v1(20.94,7.4) v1(20.94,6.6) v1(20.97,32.88) v1(20.97,32.08) v1(20.97,31.28) v1(20.97,30.48) v1(20.97,29.68) v1(20.97,28.88) v1(20.97,28.08) v1(20.97,27.28) v1(20.97,26.48) v1(20.97,25.68) v1(21.2,3.13) v1(21.2,2.13) v1(21.74,12.2) v1(21.74,11.4) v1(21.74,10.6) v1(21.74,9.8) v1(21.74,9) v1(21.74,8.2) v1(21.74,7.4) v1(21.74,6.6) v1(21.77,32.88) v1(21.77,32.08) v1(21.77,31.28) v1(21.77,30.48) v1(21.77,29.68) v1(21.77,28.88) v1(21.77,28.08) v1(21.77,27.28) v1(21.77,26.48) v1(21.77,25.68) v1(22.2,3.13) v1(22.2,2.13) v1(22.54,12.2) v1(22.54,11.4) v1(22.54,10.6) v1(22.54,9.8) v1(22.54,9) v1(22.54,8.2) v1(22.54,7.4) v1(22.54,6.6) v1(22.57,32.88) v1(22.57,32.08) v1(22.57,31.28) v1(22.57,30.48) v1(22.57,29.68) v1(22.57,28.88) v1(22.57,28.08) v1(22.57,27.28) v1(22.57,26.48) v1(22.57,25.68) v1(23.2,3.13) v1(23.2,2.13) v1(24.2,3.13) v1(24.2,2.13) v1(25.2,3.13) v1(25.2,2.13) v1(26.2,3.13) v1(26.2,2.13) v1(27.2,3.13) v1(27.2,2.13) v1(62.27,39.12) v1(62.27,38.42) v1(62.27,37.72) v1(62.27,37.02) v1(62.27,36.32) v1(62.27,35.62) v1(62.27,34.92) v1(62.27,34.22) v1(62.27,33.52) v1(62.27,32.82) v1(62.27,32.12) v1(62.27,31.42) v1(62.27,30.72) v1(62.27,30.02) v1(62.27,29.32) v1(62.27,28.62) v1(62.27,23.12) v1(62.27,22.42) v1(62.27,21.72) v1(62.27,21.02) v1(62.27,20.32) v1(62.27,19.62) v1(62.27,18.92) v1(62.27,18.22) v1(62.27,17.52) v1(62.27,16.82) v1(62.27,16.12) v1(62.27,15.42) v1(62.27,14.72) v1(62.27,14.02) v1(62.27,13.32) v1(62.27,12.62) v1(62.88,43.97) v1(62.88,42.47) v1(62.88,40.97) v1(62.88,39.47) v1(62.88,38.77) v1(62.88,38.07) v1(62.88,37.37) v1(62.88,36.67) v1(62.88,35.97) v1(62.88,35.27) v1(62.88,34.57) v1(62.88,33.87) v1(62.88,33.17) v1(62.88,32.47) v1(62.88,31.77) v1(62.88,31.07) v1(62.88,30.37) v1(62.88,29.67) v1(62.88,28.97) v1(62.88,28.27) v1(62.88,26.47) v1(62.88,24.97) v1(62.88,23.47) v1(62.88,22.77) v1(62.88,22.07) v1(62.88,21.37) v1(62.88,20.67) v1(62.88,19.97) v1(62.88,19.27) v1(62.88,18.57) v1(62.88,17.87) v1(62.88,17.17) v1(62.88,16.47) v1(62.88,15.77) v1(62.88,15.07) v1(62.88,14.37) v1(62.88,13.67) v1(62.88,12.97) v1(62.88,12.27) v1(62.88,10.77) v1(62.88,9.27) v1(62.88,7.77) v1(62.88,6.27) v1(63.49,39.12) v1(63.49,38.42) v1(63.49,37.72) v1(63.49,37.02) v1(63.49,36.32) v1(63.49,35.62) v1(63.49,34.92) v1(63.49,34.22) v1(63.49,33.52) v1(63.49,32.82) v1(63.49,32.12) v1(63.49,31.42) v1(63.49,30.72) v1(63.49,30.02) v1(63.49,29.32) v1(63.49,28.62) v1(63.49,23.12) v1(63.49,22.42) v1(63.49,21.72) v1(63.49,21.02) v1(63.49,20.32) v1(63.49,19.62) v1(63.49,18.92) v1(63.49,18.22) v1(63.49,17.52) v1(63.49,16.82) v1(63.49,16.12) v1(63.49,15.42) v1(63.49,14.72) v1(63.49,14.02) v1(63.49,13.32) v1(63.49,12.62) v1(64.1,43.97) v1(64.1,42.47) v1(64.1,40.97) v1(64.1,39.47) v1(64.1,38.77) v1(64.1,38.07) v1(64.1,37.37) v1(64.1,36.67) v1(64.1,35.97) v1(64.1,35.27) v1(64.1,34.57) v1(64.1,33.87) v1(64.1,33.17) v1(64.1,32.47) v1(64.1,31.77) v1(64.1,31.07) v1(64.1,30.37) v1(64.1,29.67) v1(64.1,28.97) v1(64.1,28.27) v1(64.1,26.47) v1(64.1,24.97) v1(64.1,23.47) v1(64.1,22.77) v1(64.1,22.07) v1(64.1,21.37) v1(64.1,20.67) v1(64.1,19.97) v1(64.1,19.27) v1(64.1,18.57) v1(64.1,17.87) v1(64.1,17.17) v1(64.1,16.47) v1(64.1,15.77) v1(64.1,15.07) v1(64.1,14.37) v1(64.1,13.67) v1(64.1,12.97) v1(64.1,12.27) v1(64.1,10.77) v1(64.1,9.27) v1(64.1,7.77) v1(64.1,6.27) v1(64.06,3.13) v1(64.06,2.13) v1(64.71,39.12) v1(64.71,38.42) v1(64.71,37.72) v1(64.71,37.02) v1(64.71,36.32) v1(64.71,35.62) v1(64.71,34.92) v1(64.71,34.22) v1(64.71,33.52) v1(64.71,32.82) v1(64.71,32.12) v1(64.71,31.42) v1(64.71,30.72) v1(64.71,30.02) v1(64.71,29.32) v1(64.71,28.62) v1(64.71,23.12) v1(64.71,22.42) v1(64.71,21.72) v1(64.71,21.02) v1(64.71,20.32) v1(64.71,19.62) v1(64.71,18.92) v1(64.71,18.22) v1(64.71,17.52) v1(64.71,16.82) v1(64.71,16.12) v1(64.71,15.42) v1(64.71,14.72) v1(64.71,14.02) v1(64.71,13.32) v1(64.71,12.62) v1(65.06,3.13) v1(65.06,2.13) v1(65.32,43.97) v1(65.32,42.47) v1(65.32,40.97) v1(65.32,39.47) v1(65.32,38.77) v1(65.32,38.07) v1(65.32,37.37) v1(65.32,36.67) v1(65.32,35.97) v1(65.32,35.27) v1(65.32,34.57) v1(65.32,33.87) v1(65.32,33.17) v1(65.32,32.47) v1(65.32,31.77) v1(65.32,31.07) v1(65.32,30.37) v1(65.32,29.67) v1(65.32,28.97) v1(65.32,28.27) v1(65.32,26.47) v1(65.32,24.97) v1(65.32,23.47) v1(65.32,22.77) v1(65.32,22.07) v1(65.32,21.37) v1(65.32,20.67) v1(65.32,19.97) v1(65.32,19.27) v1(65.32,18.57) v1(65.32,17.87) v1(65.32,17.17) v1(65.32,16.47) v1(65.32,15.77) v1(65.32,15.07) v1(65.32,14.37) v1(65.32,13.67) v1(65.32,12.97) v1(65.32,12.27) v1(65.32,10.77) v1(65.32,9.27) v1(65.32,7.77) v1(65.32,6.27) v1(65.93,39.12) v1(65.93,38.42) v1(65.93,37.72) v1(65.93,37.02) v1(65.93,36.32) v1(65.93,35.62) v1(65.93,34.92) v1(65.93,34.22) v1(65.93,33.52) v1(65.93,32.82) v1(65.93,32.12) v1(65.93,31.42) v1(65.93,30.72) v1(65.93,30.02) v1(65.93,29.32) v1(65.93,28.62) v1(65.93,23.12) v1(65.93,22.42) v1(65.93,21.72) v1(65.93,21.02) v1(65.93,20.32) v1(65.93,19.62) v1(65.93,18.92) v1(65.93,18.22) v1(65.93,17.52) v1(65.93,16.82) v1(65.93,16.12) v1(65.93,15.42) v1(65.93,14.72) v1(65.93,14.02) v1(65.93,13.32) v1(65.93,12.62) v1(66.06,3.13) v1(66.06,2.13) v1(66.54,43.97) v1(66.54,42.47) v1(66.54,40.97) v1(66.54,39.47) v1(66.54,38.77) v1(66.54,38.07) v1(66.54,37.37) v1(66.54,36.67) v1(66.54,35.97) v1(66.54,35.27) v1(66.54,34.57) v1(66.54,33.87) v1(66.54,33.17) v1(66.54,32.47) v1(66.54,31.77) v1(66.54,31.07) v1(66.54,30.37) v1(66.54,29.67) v1(66.54,28.97) v1(66.54,28.27) v1(66.54,26.47) v1(66.54,24.97) v1(66.54,23.47) v1(66.54,22.77) v1(66.54,22.07) v1(66.54,21.37) v1(66.54,20.67) v1(66.54,19.97) v1(66.54,19.27) v1(66.54,18.57) v1(66.54,17.87) v1(66.54,17.17) v1(66.54,16.47) v1(66.54,15.77) v1(66.54,15.07) v1(66.54,14.37) v1(66.54,13.67) v1(66.54,12.97) v1(66.54,12.27) v1(66.54,10.77) v1(66.54,9.27) v1(66.54,7.77) v1(66.54,6.27) v1(67.06,3.13) v1(67.06,2.13) v1(67.15,39.12) v1(67.15,38.42) v1(67.15,37.72) v1(67.15,37.02) v1(67.15,36.32) v1(67.15,35.62) v1(67.15,34.92) v1(67.15,34.22) v1(67.15,33.52) v1(67.15,32.82) v1(67.15,32.12) v1(67.15,31.42) v1(67.15,30.72) v1(67.15,30.02) v1(67.15,29.32) v1(67.15,28.62) v1(67.15,23.12) v1(67.15,22.42) v1(67.15,21.72) v1(67.15,21.02) v1(67.15,20.32) v1(67.15,19.62) v1(67.15,18.92) v1(67.15,18.22) v1(67.15,17.52) v1(67.15,16.82) v1(67.15,16.12) v1(67.15,15.42) v1(67.15,14.72) v1(67.15,14.02) v1(67.15,13.32) v1(67.15,12.62) v1(67.76,43.97) v1(67.76,42.47) v1(67.76,40.97) v1(67.76,39.47) v1(67.76,38.77) v1(67.76,38.07) v1(67.76,37.37) v1(67.76,36.67) v1(67.76,35.97) v1(67.76,35.27) v1(67.76,34.57) v1(67.76,33.87) v1(67.76,33.17) v1(67.76,32.47) v1(67.76,31.77) v1(67.76,31.07) v1(67.76,30.37) v1(67.76,29.67) v1(67.76,28.97) v1(67.76,28.27) v1(67.76,26.47) v1(67.76,24.97) v1(67.76,23.47) v1(67.76,22.77) v1(67.76,22.07) v1(67.76,21.37) v1(67.76,20.67) v1(67.76,19.97) v1(67.76,19.27) v1(67.76,18.57) v1(67.76,17.87) v1(67.76,17.17) v1(67.76,16.47) v1(67.76,15.77) v1(67.76,15.07) v1(67.76,14.37) v1(67.76,13.67) v1(67.76,12.97) v1(67.76,12.27) v1(67.76,10.77) v1(67.76,9.27) v1(67.76,7.77) v1(67.76,6.27) v1(68.06,3.13) v1(68.06,2.13) v1(68.37,39.12) v1(68.37,38.42) v1(68.37,37.72) v1(68.37,37.02) v1(68.37,36.32) v1(68.37,35.62) v1(68.37,34.92) v1(68.37,34.22) v1(68.37,33.52) v1(68.37,32.82) v1(68.37,32.12) v1(68.37,31.42) v1(68.37,30.72) v1(68.37,30.02) v1(68.37,29.32) v1(68.37,28.62) v1(68.37,23.12) v1(68.37,22.42) v1(68.37,21.72) v1(68.37,21.02) v1(68.37,20.32) v1(68.37,19.62) v1(68.37,18.92) v1(68.37,18.22) v1(68.37,17.52) v1(68.37,16.82) v1(68.37,16.12) v1(68.37,15.42) v1(68.37,14.72) v1(68.37,14.02) v1(68.37,13.32) v1(68.37,12.62)

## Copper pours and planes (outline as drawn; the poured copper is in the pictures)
VCC18R0_1 on TOP: 3.84,29.83 3.76,29.84 3.68,29.86 3.15,30.09 2.97,30.09 2.61,29.99 2.51,29.99 2.44,30.05 2.42,30.08 2.42,30.12 2.39,30.14 2.29,30.2 2.27,30.33 2.35,30.61 2.35,34.52 2.28,34.85 2.27,34.9 2.27,35.08 2.5,35.3 2.73,35.08 2.73,34.9 2.72,34.85 2.68,34.66 2.68,30.71 2.75,30.47 2.99,30.4 3.17,30.4 3.68,30.62 3.76,30.65 3.84,30.66 5.08,30.66 5.16,30.65 5.24,30.62 5.77,30.39 8.03,30.39 8.56,30.62 8.64,30.65 8.72,30.66 9.46,30.66 9.87,30.24 9.46,29.83 8.72,29.83 8.64,29.84 8.56,29.86 8.03,30.09 5.77,30.09 5.24,29.86 5.16,29.84 5.08,29.83
VCC18R0_1 on TOP: 7.76,14.85 7.7,14.86 7.66,14.89 7.64,14.91 7.61,14.95 7.6,15.01 7.6,16.15 7.64,16.26 7.75,16.3 8.05,16.3 8.16,16.26 8.2,16.15 8.2,15.01 8.19,14.95 8.16,14.91 8.14,14.89 8.1,14.86 8.04,14.85
VCC18R0_1 on CONDUCTIVE4: 2.26,6.6 2.22,6.61 2.19,6.63 0.99,7.82 0.95,7.87 0.92,8 0.92,28.95 0.93,28.99 0.95,29.02 1.94,30.01 2.24,30.45 2.28,30.5 2.34,30.53 2.46,30.56 2.59,30.51 2.64,30.46 2.68,30.4 2.72,30.38 2.76,30.34 2.83,30.23 2.83,30.11 2.79,30.03 2.73,29.96 2.29,29.66 1.42,28.79 1.42,15.86 1.86,15.42 7.36,15.42 7.85,15.49 7.89,15.49 8.09,15.39 8.13,15.17 8.09,14.95 7.89,14.85 7.85,14.85 7.36,14.92 1.85,14.92 1.42,14.49 1.42,8.1 2.42,7.1 4.1,7.1 4.73,7.73 4.73,8.71 4.88,9.01 5.19,8.88 5.43,8.42 5.65,8.42 5.89,8.88 6.22,9 6.33,8.66 6.03,8.06 6.03,7.27 6.02,7.23 6,7.2 5.43,6.63 5.4,6.61 5.36,6.6
CSA on TOP: 9.5,14.25 9.39,14.29 9.35,14.4 9.35,17.7 9.39,17.81 9.5,17.85 10.95,17.85 11.06,17.81 11.1,17.7 11.1,14.4 11.06,14.29 10.95,14.25
CSA on TOP: 2.35,35.7 2.24,35.74 2.2,35.85 2.2,36.14 2.21,36.2 2.24,36.24 2.25,37.33 2.27,37.42 2.32,37.5 2.88,38.05 2.88,38.64 2.89,38.7 2.92,38.74 3.33,39.15 3.33,39.83 3.24,39.91 3.21,39.95 3.2,40.01 3.2,41.3 3.24,41.41 3.35,41.45 9.3,41.45 9.41,41.41 9.45,41.3 9.45,40.25 9.41,40.14 9.3,40.1 5.5,40.1 5.34,39.94 5.3,39.91 5.24,39.9 3.88,39.9 3.83,39.85 3.83,38.8 3.91,38.72 3.94,38.67 3.95,38.61 3.95,38.48 3.94,38.43 3.91,38.38 2.75,37.22 2.75,36.25 2.79,36.2 2.8,36.14 2.8,35.85 2.76,35.74 2.65,35.7
CSB on TOP: 11.33,9.56 11.27,9.57 11.23,9.6 11.19,9.64 10,9.64 9.89,9.68 9.85,9.79 9.85,11.54 9.86,11.6 9.89,11.64 11.8,13.55 11.8,16.75 11.84,16.86 11.95,16.9 13,16.9 13.11,16.86 13.15,16.75 13.15,11.69 13.14,11.63 13.11,11.59 12.17,10.65 12.17,10.1 12.16,10.04 12.13,10 11.73,9.6 11.69,9.57 11.63,9.56
CSB on TOP: 14.33,29.44 14.28,29.53 14.25,29.54 14.23,29.56 14.19,29.57 14.16,29.6 14.12,29.66 14.12,29.74 14.28,30.15 14.28,30.25 14.21,30.57 14.2,30.62 14.2,30.8 14.27,30.96 14.43,31.02 14.6,31.02 14.65,31.02 14.86,30.98 15.14,30.98 15.52,31.09 15.56,31.1 15.6,31.1 15.8,31.1 16.07,30.82 15.8,30.55 15.6,30.55 15.56,30.55 15.52,30.56 15.23,30.65 14.98,30.65 14.64,30.57 14.6,30.36 14.6,30.22 14.78,29.74 14.78,29.66 14.74,29.6 14.71,29.57 14.67,29.56 14.65,29.54 14.61,29.52 14.57,29.52 14.52,29.43 14.43,29.4
GDA on TOP: 1.63,23.73 1.58,23.81 1.32,24.77 1.19,24.89 1.16,24.94 1.15,25 1.15,28.45 1.16,28.51 1.19,28.56 1.7,29.07 1.75,29.1 1.8,29.11 4.34,29.11 4.62,28.84 4.34,28.56 1.62,28.56 1.45,28.39 1.45,25.06 1.53,24.98 2.49,24.72 2.53,24.71 2.59,24.52 2.42,24.43 2,24.55 1.75,24.3 1.87,23.88 1.87,23.84 1.86,23.8 1.81,23.72 1.72,23.69
GDB on TOP: 2.85,13.06 2.85,15.9 2.75,16 2.72,16.05 2.71,16.11 2.71,16.9 2.75,17.01 2.86,17.05 3.2,17.05 3.31,17.01 3.35,16.9 3.35,14.55 3.34,14.49 3.31,14.45 3.15,14.29 3.15,13.06 3.76,12.06 3.78,12.02 3.78,11.98 3.7,11.85 3.55,11.86 3.52,11.88 3.5,11.91 3.25,12.32 2.75,12.32 2.49,11.9 2.29,11.86 2.24,12.06
PN on TOP: 13.8,10.7 13.69,10.74 13.65,10.85 13.65,16.75 13.69,16.86 13.8,16.9 14.85,16.9 14.96,16.86 15,16.75 15,10.85 14.96,10.74 14.85,10.7
PN on TOP: 5.05,10.69 4.99,10.7 4.95,10.73 4.59,11.09 4.56,11.13 4.55,11.19 4.55,18.99 4.56,19.05 4.59,19.09 4.8,19.3 4.8,24.04 4.81,24.1 4.84,24.14 5.65,24.95 5.65,27.07 5.43,27.28 3.38,27.28 2.94,26.84 2.9,26.81 2.84,26.8 2.45,26.8 2.34,26.84 2.3,26.95 2.3,28.05 2.34,28.16 2.45,28.2 2.8,28.2 2.86,28.19 2.91,28.16 3.21,27.86 6.21,27.86 6.26,27.85 6.31,27.81 6.78,27.34 6.81,27.3 6.83,27.24 6.83,24.43 6.81,24.33 6.75,24.25 5.97,23.47 5.7,22.96 5.7,19.3 6.41,18.59 6.44,18.55 6.45,18.49 6.45,13.24 6.46,13.22 6.46,13.19 6.46,11.11 6.45,11.05 6.42,11.01 6.14,10.73 6.1,10.7 6.04,10.69
PN on TOP: 4.4,41.95 4.29,41.99 4.25,42.1 4.25,44.3 4.29,44.41 4.4,44.45 9.35,44.45 9.46,44.41 9.5,44.3 9.5,42.1 9.46,41.99 9.35,41.95
PN on TOP: 40.16,40.15 40.1,40.16 40.06,40.19 38.6,41.65 35.31,41.65 35.25,41.66 35.21,41.69 35.04,41.86 35.01,41.9 35,41.96 35,42.64 35.01,42.7 35.04,42.74 35.11,42.81 35.15,42.84 35.21,42.85 35.64,42.85 35.7,42.84 35.74,42.81 35.81,42.74 35.84,42.7 35.85,42.64 35.85,42.4 36.05,42.2 38.65,42.2 39.56,43.11 39.6,43.14 39.66,43.15 43.65,43.15 43.76,43.11 43.8,43 43.8,40.3 43.76,40.19 43.65,40.15
PN on CONDUCTIVE2, CONDUCTIVE5: outline of 141 points within 0.55,16 24.5,42.45 ; 2 cut-outs
SIG0017 on TOP: 21.05,20.4 20.87,20.47 20.8,20.65 20.8,23.55 20.87,23.73 21.05,23.8 23.4,23.8 23.49,23.78 23.57,23.73 24.43,22.87 24.48,22.79 24.5,22.7 24.5,20.65 24.43,20.47 24.25,20.4
SIG0017 on TOP: 16.8,21.5 16.69,21.54 16.65,21.65 16.65,23.14 16.66,23.2 16.69,23.24 17.36,23.91 17.4,23.94 17.46,23.95 19.25,23.95 19.36,23.91 19.4,23.8 19.4,21.65 19.36,21.54 19.25,21.5
SIG0019 on TOP: 10.55,20.21 10.55,20.25 10.56,20.3 10.7,20.88 10.7,21.49 10.61,21.58 10.56,21.66 10.54,21.75 10.54,22.62 10.56,22.71 10.61,22.79 11.1,23.28 11.1,24.16 9.77,25.49 9.25,25.8 9.19,25.85 9.15,25.91 9.14,26.1 9.26,26.24 9.3,26.26 9.35,26.27 9.36,26.31 9.37,26.35 9.52,26.48 9.71,26.46 9.77,26.42 9.81,26.37 10.12,25.85 13.04,25.85 13.22,26.03 13.22,27.1 13.47,27.35 13.72,27.1 13.72,26.22 14.16,25.79 14.19,25.74 14.2,25.68 14.2,25.44 14.16,25.33 14.05,25.29 11.21,25.29 11.09,25.17 11.09,24.88 11.53,24.44 11.58,24.36 11.6,24.27 11.6,23.02 11.8,22.82 11.85,22.74 11.87,22.65 11.87,22.24 11.85,22.15 11.8,22.07 11.2,21.47 11.2,20.88 11.34,20.3 11.35,20.25 11.35,20.21 11.35,19.9 10.95,19.5 10.55,19.9
SIG00110 on TOP: 17.05,35.6 16.94,35.64 16.9,35.75 16.9,37.09 16.91,37.15 16.94,37.19 18.4,38.65 18.4,40 18.44,40.11 18.55,40.15 19.45,40.15 19.56,40.11 19.6,40 19.6,38.46 19.59,38.4 19.56,38.36 17.7,36.5 17.7,35.75 17.66,35.64 17.55,35.6
SIG00112 on TOP: 7.46,28.44 7.4,28.45 7.36,28.48 7.23,28.61 7.2,28.65 7.19,28.71 7.19,28.94 7.2,29 7.23,29.04 7.34,29.16 7.39,29.19 7.45,29.2 7.64,29.2 7.7,29.19 7.74,29.16 7.75,29.15 10.49,29.15 11,29.65 11,32.92 10.86,33.5 10.85,33.55 10.85,33.59 10.85,34.21 10.85,34.25 10.86,34.3 11,34.88 11,35.1 10.85,35.89 10.85,35.92 10.85,36.25 11.25,36.65 11.65,36.25 11.65,35.92 11.65,35.89 11.64,35.85 11.5,35.1 11.5,34.88 11.64,34.3 11.65,34.25 11.65,34.21 11.65,33.59 11.65,33.55 11.64,33.5 11.5,32.92 11.5,29.55 11.48,29.45 11.43,29.37 10.66,28.61 10.58,28.56 10.49,28.54 7.85,28.54 7.79,28.48 7.75,28.45 7.69,28.44
SIG00112 on TOP: 5.65,35.1 5.53,35.13 5.43,35.23 5.4,35.35 5.4,38 5.14,38.26 5.11,38.3 5.1,38.36 5.1,38.45 5.14,38.56 5.25,38.6 5.97,38.6 6.08,38.56 6.12,38.45 6.12,38.31 6.11,38.25 6.08,38.21 5.88,38 5.88,35.8 5.97,35.7 6.75,35.7 6.86,35.66 6.9,35.55 6.9,35.25 6.86,35.14 6.75,35.1
SIG00119 on TOP: 7.77,16.7 7.66,16.74 7.62,16.85 7.62,19.5 7.53,19.59 7.5,19.63 7.49,19.69 7.49,24.14 7.22,24.41 7.19,24.45 7.17,24.51 7.17,26.73 7.19,26.82 8.14,27.8 8.19,27.83 8.25,27.84 10.28,27.84 10.32,27.84 10.36,27.83 10.58,27.76 11.43,28.25 11.46,28.26 11.5,28.27 11.64,28.16 11.57,27.99 11.21,27.78 11.21,27.71 12,27.71 12.15,27.57 12,27.41 11.22,27.41 11.57,27.21 11.64,27.04 11.5,26.93 11.46,26.94 11.43,26.95 10.66,27.39 10.36,27.3 10.32,27.29 10.28,27.29 8.34,27.29 7.67,26.62 7.67,24.8 8.37,24.11 8.4,24.06 8.41,24.01 8.41,23.1 8.41,23.05 8.4,23 8.4,19.78 8.39,19.72 8.36,19.68 8.18,19.5 8.18,16.85 8.14,16.74 8.03,16.7
SIG00120 on TOP: 54.25,14.4 54.14,14.44 54.1,14.55 54.1,14.6 53.35,15.35 46.8,15.35 46.69,15.39 46.65,15.5 46.65,22.9 46.69,23.01 46.8,23.05 54.49,23.05 54.55,23.04 54.59,23.01 56.2,21.4 58.99,21.4 59.1,21.36 59.14,21.25 59.14,14.55 59.1,14.44 58.99,14.4
SIG00120 on BOTTOM: 36.1,0.5 35.99,0.54 35.95,0.65 35.95,3.69 35.96,3.75 35.99,3.79 36.25,4.05 36.25,5.91 36.26,5.97 36.29,6.01 38.94,8.66 38.94,13.58 38.95,13.64 38.98,13.68 47.96,22.66 48,22.69 48.06,22.7 56.9,22.7 57.01,22.66 57.05,22.55 57.05,15.37 57.01,15.26 56.9,15.22 49.72,15.22 45.3,10.8 45.3,8.16 45.29,8.1 45.26,8.06 42.77,5.57 42.73,5.54 42.67,5.53 41.31,5.53 40.7,4.92 40.7,4.02 40.91,3.81 40.94,3.77 40.95,3.71 40.95,0.65 40.91,0.54 40.8,0.5
SIG00120 on CONDUCTIVE3, CONDUCTIVE4: 36.1,0.5 35.99,0.54 35.95,0.65 35.95,3.72 35.96,3.76 35.98,3.79 36.17,3.98 36.2,4 36.24,4.01 40.67,4.01 40.71,4 40.74,3.98 40.91,3.81 40.95,3.71 40.95,0.65 40.91,0.54 40.8,0.5
SIG00120 on CONDUCTIVE5: 36.1,0.5 35.99,0.54 35.95,0.65 35.95,3.71 35.96,3.75 35.98,3.78 36.25,4.05 36.25,5.93 36.26,5.97 36.28,6 38.94,8.66 38.94,13.65 38.95,13.69 38.97,13.72 48.02,22.77 48.05,22.79 48.09,22.8 52.51,22.8 52.58,22.77 52.61,22.7 52.61,15.35 52.58,15.28 52.51,15.25 49.75,15.25 45.3,10.8 45.3,8.14 45.29,8.1 45.27,8.07 42.76,5.56 42.73,5.54 42.69,5.53 41.31,5.53 40.7,4.92 40.7,4.02 40.91,3.81 40.94,3.77 40.95,3.71 40.95,0.65 40.91,0.54 40.8,0.5
SIG00125 on TOP: 27.35,27.95 27.24,27.99 27.2,28.1 27.2,40.65 27.24,40.76 27.35,40.8 32.34,40.8 32.4,40.79 32.44,40.76 34.05,39.15 37.44,39.15 37.5,39.14 37.54,39.11 39,37.65 42.1,37.65 42.21,37.61 42.25,37.5 42.25,29.3 42.21,29.19 42.1,29.15 38.85,29.15 37.69,27.99 37.65,27.96 37.59,27.95
SIG00125 on BOTTOM: 26.45,27.95 26.34,27.99 26.3,28.1 26.3,40.9 26.34,41.01 26.45,41.05 28.24,41.05 28.3,41.04 28.34,41.01 28.65,40.7 30.6,40.7 30.91,41.01 30.95,41.04 31.01,41.05 32.64,41.05 32.7,41.04 32.74,41.01 34.25,39.5 36.7,39.5 38.21,41.01 38.25,41.04 38.31,41.05 42.1,41.05 42.21,41.01 42.25,40.9 42.25,28.61 42.24,28.55 42.21,28.51 41.69,27.99 41.65,27.96 41.59,27.95
SIG00125 on CONDUCTIVE2, CONDUCTIVE3, CONDUCTIVE4, CONDUCTIVE5: 27.64,29.3 27.6,29.31 27.57,29.33 27.24,29.66 27.21,29.7 27.2,29.76 27.2,39.3 27.24,39.41 27.35,39.45 38.19,39.45 38.25,39.44 38.29,39.41 38.49,39.21 38.52,39.17 38.53,39.11 38.53,30.74 38.49,30.64 37.19,29.34 37.09,29.3
SIG00130 on TOP: 46.75,29.15 46.64,29.19 46.6,29.3 46.6,34.8 46.64,34.91 46.75,34.95 47.75,34.95 51.3,38.5 51.3,45.1 51.34,45.21 51.45,45.25 58.95,45.25 59.06,45.21 59.1,45.1 59.1,30.55 59.06,30.44 58.95,30.4 55.7,30.4 54.49,29.19 54.45,29.16 54.39,29.15
SIG00130 on CONDUCTIVE2: 48.65,0.5 48.54,0.54 48.5,0.65 48.5,3.71 48.51,3.75 48.53,3.78 48.71,3.96 48.71,10.15 48.72,10.19 48.74,10.22 54.08,15.56 54.08,26.02 51,29.1 48.9,29.1 48.83,29.13 48.8,29.2 48.8,36.7 48.83,36.77 48.9,36.8 59.01,36.8 59.08,36.77 59.11,36.7 59.11,14.97 59.1,14.93 59.08,14.9 53.27,9.09 53.27,3.98 53.46,3.79 53.5,3.69 53.5,0.65 53.46,0.54 53.35,0.5
SIG00130 on CONDUCTIVE3, CONDUCTIVE4: 48.65,0.5 48.54,0.54 48.5,0.65 48.5,3.71 48.51,3.75 48.53,3.78 48.71,3.96 48.71,10.15 48.72,10.19 48.74,10.22 54.08,15.56 54.08,26.02 51,29.1 48.9,29.1 48.83,29.13 48.8,29.2 48.8,36.7 48.83,36.77 48.9,36.8 59.01,36.8 59.08,36.77 59.11,36.7 59.11,14.97 59.1,14.93 59.08,14.9 53.27,9.09 53.27,3.98 53.46,3.79 53.5,3.69 53.5,0.65 53.46,0.54 53.35,0.5
SIG00131 on TOP: 27.35,11.9 27.24,11.94 27.2,12.05 27.2,25.3 27.24,25.41 27.35,25.45 37.54,25.45 37.6,25.44 37.64,25.41 40,23.05 42.1,23.05 42.21,23.01 42.25,22.9 42.25,15.45 42.21,15.34 42.1,15.3 34.53,15.3 33.05,13.82 33.05,12.56 33.04,12.5 33.01,12.46 32.49,11.94 32.45,11.91 32.39,11.9
SIG00131 on BOTTOM: 26.45,10.05 26.34,10.09 26.3,10.2 26.3,25.3 26.34,25.41 26.45,25.45 40.49,25.45 40.55,25.44 40.59,25.41 42.21,23.79 42.24,23.75 42.25,23.69 42.25,20.56 42.24,20.5 42.21,20.46 36.34,14.59 36.3,14.56 36.24,14.55 34.65,14.55 33,12.9 33,10.2 32.96,10.09 32.85,10.05
SIG00132 on TOP: 14.7,0.5 14.59,0.54 14.55,0.65 14.55,3.69 14.56,3.75 14.59,3.79 14.76,3.96 14.76,9.47 14.77,9.53 14.8,9.57 16.94,11.71 16.94,16.08 16.95,16.14 16.98,16.18 18.16,17.36 18.2,17.39 18.26,17.4 24.32,17.4 24.43,17.36 24.47,17.25 24.47,8.97 25.1,8.34 25.13,8.3 25.14,8.24 25.14,6.76 25.7,6.2 28.04,6.2 28.15,6.16 28.19,6.05 28.19,4.07 28.46,3.8 28.49,3.76 28.5,3.7 28.5,0.65 28.46,0.54 28.35,0.5
SIG00132 on TOP, CONDUCTIVE2, CONDUCTIVE3, CONDUCTIVE4, CONDUCTIVE5: 62.65,0.5 62.54,0.54 62.5,0.65 62.5,3.69 62.51,3.75 62.54,3.79 62.91,4.16 62.91,4.74 61.88,5.77 61.85,5.81 61.84,5.87 61.84,45.35 61.88,45.46 61.99,45.5 68.74,45.5 68.8,45.49 68.84,45.46 69.41,44.89 69.44,44.85 69.45,44.79 69.45,4.15 69.49,4.1 69.5,4.04 69.5,0.65 69.46,0.54 69.35,0.5
SIG00132 on BOTTOM: 62.65,0.5 62.54,0.54 62.5,0.65 62.5,3.69 62.51,3.75 62.54,3.79 62.91,4.16 62.91,4.74 61.84,5.81 61.81,5.85 61.8,5.91 61.8,10.4 59.69,12.51 59.66,12.55 59.65,12.61 59.65,45.35 59.69,45.46 59.8,45.5 68.39,45.5 68.45,45.49 68.49,45.46 69.41,44.54 69.44,44.5 69.45,44.44 69.45,4.15 69.49,4.1 69.5,4.04 69.5,0.65 69.46,0.54 69.35,0.5
SIG00132 on BOTTOM: 25.7,6.2 28.04,6.2 28.15,6.16 28.19,6.05 28.19,4.08 28.34,3.93 28.37,3.89 28.46,3.8 28.49,3.75 28.5,3.69 28.5,0.65 28.46,0.54 28.35,0.5 14.7,0.5 14.59,0.54 14.55,0.65 14.55,3.69 14.56,3.75 14.59,3.79 14.76,3.96 14.76,9.46 14.77,9.52 14.8,9.56 16.94,11.7 16.94,16.5 16.95,16.56 16.98,16.6 17.8,17.42 17.8,33.15 17.84,33.26 17.95,33.3 23.64,33.3 23.75,33.26 23.79,33.15 23.79,8.11 ; 1 cut-out
SIG00132 on CONDUCTIVE2, CONDUCTIVE3, CONDUCTIVE4: 18.2,33.15 18.23,33.22 18.3,33.25 22.85,33.25 22.92,33.22 22.95,33.15 22.95,28.5 23.7,27.75 38.05,27.75 41.12,30.82 41.15,30.84 41.19,30.85 46.21,30.85 46.25,30.84 46.28,30.82 47.27,29.83 47.29,29.8 47.3,29.76 47.3,29.2 47.77,28.07 48.9,27.6 49.46,27.6 49.5,27.59 49.53,27.57 49.72,27.38 49.74,27.35 49.75,27.31 49.75,24.59 49.74,24.55 49.72,24.52 49.29,24.09 49.27,24.08 49.25,24.07 48.49,23.61 48.03,22.85 48.02,22.83 48.01,22.81 46.88,21.68 46.85,21.66 46.81,21.65 41.99,21.65 41.95,21.66 41.92,21.68 38.1,25.5 23.2,25.5 23.03,25.33 23,25.31 22.96,25.3 18.3,25.3 18.23,25.33 18.2,25.4 ; 1 cut-out
SIG00132 on CONDUCTIVE2, CONDUCTIVE3, CONDUCTIVE4, CONDUCTIVE5: 14.65,0.5 14.58,0.53 14.55,0.6 14.55,3.71 14.56,3.75 14.58,3.78 14.77,3.97 14.8,3.99 14.84,4 28.21,4 28.25,3.99 28.28,3.97 28.47,3.78 28.49,3.75 28.5,3.71 28.5,0.6 28.47,0.53 28.4,0.5

Small or netless copper shapes (teardrops, artwork), in the pictures only: 40 on TOP, 6 on BOTTOM, 8 on CONDUCTIVE3, 7 on CONDUCTIVE4, 1 on CONDUCTIVE2, 2 on CONDUCTIVE5

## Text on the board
SYMBOL-2-TOP: D606 | R602 | D605 | DP604 | C605 | C604 | C603 | IC601 | C607 | D611 | R607 | D610 | D609 | D604 | R617 | DP609 | CN602 | R608 | R604 | R612 | R613 | DP605 | D603 | L602 | L601 | R605 | DP610 | DP606 | Q602 | DP608 | DP612 | DP611 | R615 | C609 | D608 | D602 | Q601 | DP607 | R616 | T602 | T601 | D601 | D607 | C610 | DP613 | CN601 | DP601 | R618 | R609 | C601 | C602 | DP602 | R619 | R601 | R623 | DP603 | R622 | R610 | D612 | DP615 | R614 | C612 | DP614 | R606 | C611 | C608 | C606 | R611 | R603 | 2 | 1 | CSB | CSA | QA-G | QA-S | QB-S | QB-G | QB-D | QA-D | SGB009601000 | SAA009601010 | PFCOUT | PN | VIN_B | VIN_A | RD244 PFCunit
User.5: heatsink
